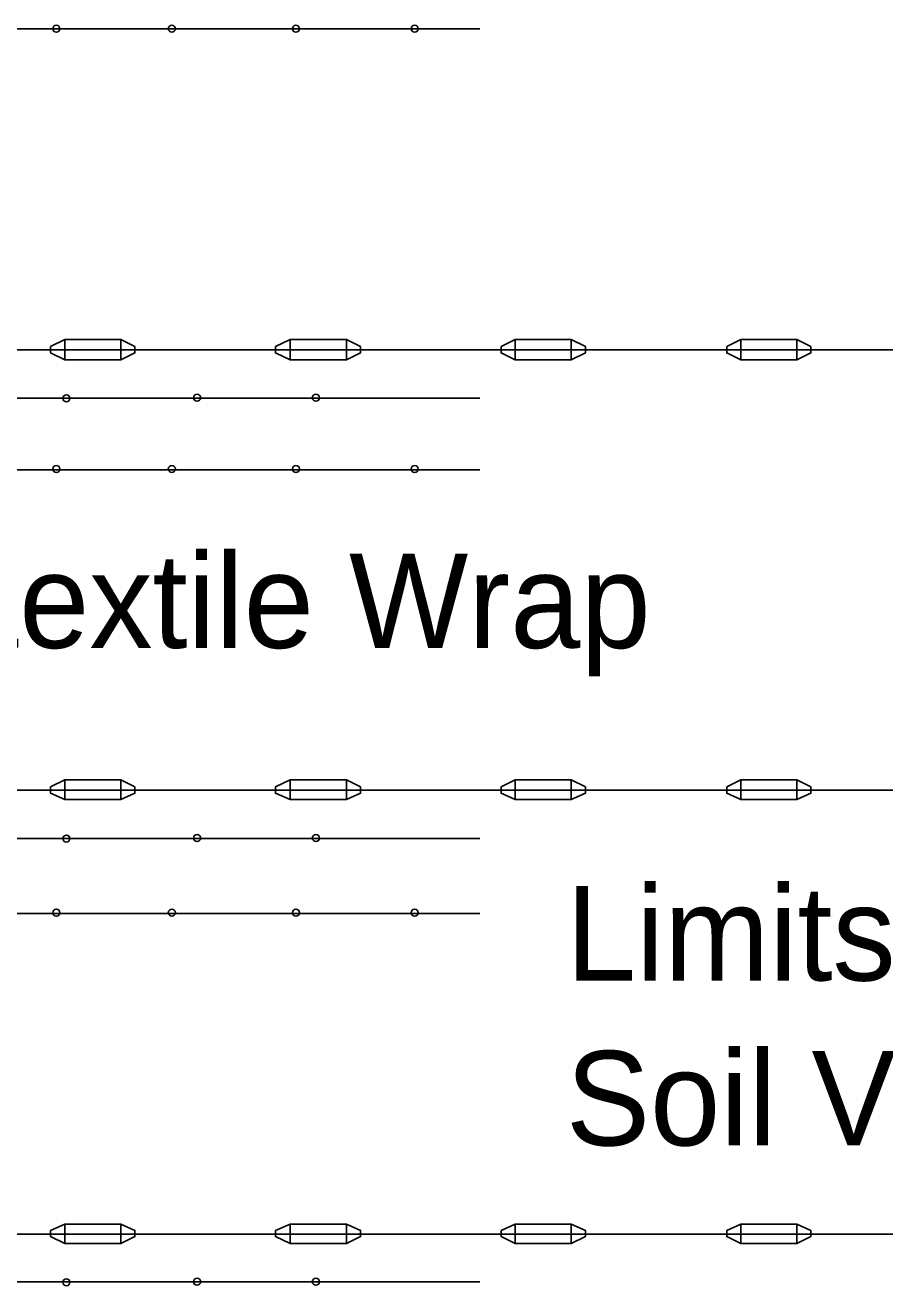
# Model space of a CAD drawing. Extents: x 126777.1 to 126780.68, y 176294.14 to 176295.44.
# Drawn here: x 126779.2844 to 126779.3418, y 176295.1145 to 176295.1986 of the extents above; entities that cross this region are included whole.
import ezdxf

# ---------------------------------------------------------------- set-up
doc = ezdxf.new("R2010")
doc.units = 0
for name, color, linetype in [('Miscellaneous', 7, 'Continuous'), ('Patterning', 7, 'Continuous'), ('TextMisc', 7, 'Continuous')]:
    doc.layers.add(name, color=color, linetype=linetype)

msp = doc.modelspace()

# ---------------------------------------------------------------- linework, layer by layer
at = {"layer": 'Miscellaneous'}
for p, q in [((126779.24097118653, 176295.17692708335), (126779.3821691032, 176295.17692708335)), ((126779.24097118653, 176295.14755208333), (126779.3821691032, 176295.14755208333)), ((126779.24097118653, 176295.11791666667), (126779.3821691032, 176295.11791666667))]:
    msp.add_line(p, q, dxfattribs=at)
for points in [[(126779.28612743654, 176295.17713541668), (126779.28706493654, 176295.17760416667), (126779.28706493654, 176295.17625000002), (126779.28612743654, 176295.17671875)], [(126779.28706493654, 176295.17760416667), (126779.29081493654, 176295.17760416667), (126779.29081493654, 176295.17625000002), (126779.28706493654, 176295.17625000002)], [(126779.29081493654, 176295.17760416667), (126779.29175243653, 176295.17713541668), (126779.29175243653, 176295.17671875), (126779.29081493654, 176295.17625000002)], [(126779.30112743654, 176295.17713541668), (126779.30211701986, 176295.17760416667), (126779.30211701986, 176295.17625000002), (126779.30112743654, 176295.17671875)], [(126779.30211701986, 176295.17760416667), (126779.30586701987, 176295.17760416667), (126779.30586701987, 176295.17625000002), (126779.30211701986, 176295.17625000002)], [(126779.30586701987, 176295.17760416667), (126779.30680451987, 176295.17713541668), (126779.30680451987, 176295.17671875), (126779.30586701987, 176295.17625000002)], [(126779.31617951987, 176295.17713541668), (126779.31711701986, 176295.17760416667), (126779.31711701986, 176295.17625000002), (126779.31617951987, 176295.17671875)], [(126779.31711701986, 176295.17760416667), (126779.32086701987, 176295.17760416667), (126779.32086701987, 176295.17625000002), (126779.31711701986, 176295.17625000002)], [(126779.32086701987, 176295.17760416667), (126779.32180451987, 176295.17713541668), (126779.32180451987, 176295.17671875), (126779.32086701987, 176295.17625000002)], [(126779.3312316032, 176295.17713541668), (126779.3321691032, 176295.17760416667), (126779.3321691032, 176295.17625000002), (126779.3312316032, 176295.17671875)], [(126779.3321691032, 176295.17760416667), (126779.3359191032, 176295.17760416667), (126779.3359191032, 176295.17625000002), (126779.3321691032, 176295.17625000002)], [(126779.3359191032, 176295.17760416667), (126779.3368566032, 176295.17713541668), (126779.3368566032, 176295.17671875), (126779.3359191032, 176295.17625000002)], [(126779.28612743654, 176295.14776041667), (126779.28706493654, 176295.14822916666), (126779.28706493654, 176295.14692708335), (126779.28612743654, 176295.14734375)], [(126779.28706493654, 176295.14822916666), (126779.29081493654, 176295.14822916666), (126779.29081493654, 176295.14692708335), (126779.28706493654, 176295.14692708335)], [(126779.29081493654, 176295.14822916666), (126779.29175243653, 176295.14776041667), (126779.29175243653, 176295.14734375), (126779.29081493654, 176295.14692708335)], [(126779.30112743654, 176295.14776041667), (126779.30211701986, 176295.14822916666), (126779.30211701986, 176295.14692708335), (126779.30112743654, 176295.14734375)], [(126779.30211701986, 176295.14822916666), (126779.30586701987, 176295.14822916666), (126779.30586701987, 176295.14692708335), (126779.30211701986, 176295.14692708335)], [(126779.30586701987, 176295.14822916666), (126779.30680451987, 176295.14776041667), (126779.30680451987, 176295.14734375), (126779.30586701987, 176295.14692708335)], [(126779.31617951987, 176295.14776041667), (126779.31711701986, 176295.14822916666), (126779.31711701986, 176295.14692708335), (126779.31617951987, 176295.14734375)], [(126779.31711701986, 176295.14822916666), (126779.32086701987, 176295.14822916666), (126779.32086701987, 176295.14692708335), (126779.31711701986, 176295.14692708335)], [(126779.32086701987, 176295.14822916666), (126779.32180451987, 176295.14776041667), (126779.32180451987, 176295.14734375), (126779.32086701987, 176295.14692708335)], [(126779.3312316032, 176295.14776041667), (126779.3321691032, 176295.14822916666), (126779.3321691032, 176295.14692708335), (126779.3312316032, 176295.14734375)], [(126779.3321691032, 176295.14822916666), (126779.3359191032, 176295.14822916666), (126779.3359191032, 176295.14692708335), (126779.3321691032, 176295.14692708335)], [(126779.3359191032, 176295.14822916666), (126779.3368566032, 176295.14776041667), (126779.3368566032, 176295.14734375), (126779.3359191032, 176295.14692708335)], [(126779.28612743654, 176295.11817708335), (126779.28706493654, 176295.11859375), (126779.28706493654, 176295.11729166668), (126779.28612743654, 176295.11776041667)], [(126779.28706493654, 176295.11859375), (126779.29081493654, 176295.11859375), (126779.29081493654, 176295.11729166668), (126779.28706493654, 176295.11729166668)], [(126779.29081493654, 176295.11859375), (126779.29175243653, 176295.11817708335), (126779.29175243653, 176295.11776041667), (126779.29081493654, 176295.11729166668)], [(126779.30112743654, 176295.11817708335), (126779.30211701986, 176295.11859375), (126779.30211701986, 176295.11729166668), (126779.30112743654, 176295.11776041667)], [(126779.30211701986, 176295.11859375), (126779.30586701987, 176295.11859375), (126779.30586701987, 176295.11729166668), (126779.30211701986, 176295.11729166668)], [(126779.30586701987, 176295.11859375), (126779.30680451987, 176295.11817708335), (126779.30680451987, 176295.11776041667), (126779.30586701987, 176295.11729166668)], [(126779.31617951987, 176295.11817708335), (126779.31711701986, 176295.11859375), (126779.31711701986, 176295.11729166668), (126779.31617951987, 176295.11776041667)], [(126779.31711701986, 176295.11859375), (126779.32086701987, 176295.11859375), (126779.32086701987, 176295.11729166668), (126779.31711701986, 176295.11729166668)], [(126779.32086701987, 176295.11859375), (126779.32180451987, 176295.11817708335), (126779.32180451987, 176295.11776041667), (126779.32086701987, 176295.11729166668)], [(126779.3312316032, 176295.11817708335), (126779.3321691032, 176295.11859375), (126779.3321691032, 176295.11729166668), (126779.3312316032, 176295.11776041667)], [(126779.3321691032, 176295.11859375), (126779.3359191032, 176295.11859375), (126779.3359191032, 176295.11729166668), (126779.3321691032, 176295.11729166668)], [(126779.3359191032, 176295.11859375), (126779.3368566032, 176295.11817708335), (126779.3368566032, 176295.11776041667), (126779.3359191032, 176295.11729166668)]]:
    msp.add_lwpolyline(points, close=True, dxfattribs=at)
at = {"layer": 'Patterning'}
for p, q in [((126779.31477326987, 176295.19833333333), (126779.25581493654, 176295.19833333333)), ((126779.2410753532, 176295.17369791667), (126779.31477326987, 176295.17369791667)), ((126779.31477326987, 176295.16890625), (126779.25581493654, 176295.16890625)), ((126779.2410753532, 176295.14432291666), (126779.31477326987, 176295.14432291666)), ((126779.31477326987, 176295.1393229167), (126779.25581493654, 176295.1393229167)), ((126779.2410753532, 176295.11473958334), (126779.31477326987, 176295.11473958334))]:
    msp.add_line(p, q, dxfattribs=at)
for centre, radius, start, end in [((126779.28650547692, 176295.19834467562), 0.00023464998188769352, 0, 180), ((126779.28650547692, 176295.19834467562), 0.00023464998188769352, 180, 0), ((126779.2942136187, 176295.19834467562), 0.0002346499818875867, 0, 180), ((126779.2942136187, 176295.19834467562), 0.0002346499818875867, 180, 0), ((126779.30249415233, 176295.19834467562), 0.00023464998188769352, 0, 180), ((126779.30249415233, 176295.19834467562), 0.00023464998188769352, 180, 0), ((126779.31041589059, 176295.19834467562), 0.00023464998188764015, 0, 180), ((126779.31041589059, 176295.19834467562), 0.00023464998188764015, 180, 0), ((126779.28717844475, 176295.17368753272), 0.00023464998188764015, 0, 180), ((126779.29590189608, 176295.17372518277), 0.00023464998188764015, 0, 180), ((126779.30382363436, 176295.17372518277), 0.00023464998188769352, 0, 180), ((126779.28717844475, 176295.17368753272), 0.00023464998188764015, 180, 0), ((126779.29590189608, 176295.17372518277), 0.00023464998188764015, 180, 0), ((126779.30382363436, 176295.17372518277), 0.00023464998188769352, 180, 0), ((126779.28650547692, 176295.16897071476), 0.00023464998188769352, 0, 180), ((126779.28650547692, 176295.16897071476), 0.00023464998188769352, 180, 0), ((126779.2942136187, 176295.16897071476), 0.0002346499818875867, 0, 180), ((126779.2942136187, 176295.16897071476), 0.0002346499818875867, 180, 0), ((126779.30249415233, 176295.16897071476), 0.00023464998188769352, 0, 180), ((126779.30249415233, 176295.16897071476), 0.00023464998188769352, 180, 0), ((126779.31041589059, 176295.16897071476), 0.00023464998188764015, 0, 180), ((126779.31041589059, 176295.16897071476), 0.00023464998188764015, 180, 0), ((126779.28717844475, 176295.14431357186), 0.00023464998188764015, 0, 180), ((126779.29590189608, 176295.14435122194), 0.00023464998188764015, 0, 180), ((126779.30382363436, 176295.14435122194), 0.00023464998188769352, 0, 180), ((126779.28717844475, 176295.14431357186), 0.00023464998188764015, 180, 0), ((126779.29590189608, 176295.14435122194), 0.00023464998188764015, 180, 0), ((126779.30382363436, 176295.14435122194), 0.00023464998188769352, 180, 0), ((126779.28650547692, 176295.13937250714), 0.00023464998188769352, 0, 180), ((126779.2942136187, 176295.13937250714), 0.0002346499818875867, 0, 180), ((126779.30249415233, 176295.13937250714), 0.00023464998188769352, 0, 180), ((126779.31041589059, 176295.13937250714), 0.00023464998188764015, 0, 180), ((126779.28650547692, 176295.13937250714), 0.00023464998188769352, 180, 0), ((126779.2942136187, 176295.13937250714), 0.0002346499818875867, 180, 0), ((126779.30249415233, 176295.13937250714), 0.00023464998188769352, 180, 0), ((126779.31041589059, 176295.13937250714), 0.00023464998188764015, 180, 0), ((126779.28717844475, 176295.1147153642), 0.00023464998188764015, 0, 180), ((126779.28717844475, 176295.1147153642), 0.00023464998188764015, 180, 0), ((126779.29590189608, 176295.1147530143), 0.00023464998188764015, 0, 180), ((126779.29590189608, 176295.1147530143), 0.00023464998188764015, 180, 0), ((126779.30382363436, 176295.1147530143), 0.00023464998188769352, 0, 180), ((126779.30382363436, 176295.1147530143), 0.00023464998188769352, 180, 0)]:
    msp.add_arc(centre, radius, start, end, dxfattribs=at)

# ---------------------------------------------------------------- texts
at = {"layer": 'TextMisc'}
for s, p in [('Geotextile Wrap', (126779.2657628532, 176295.15703125)), ('Limits of ', (126779.32050324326, 176295.13484582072)), ('Soil Volume', (126779.32050324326, 176295.12384579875))]:
    msp.add_text(s, height=0.0063000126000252, dxfattribs=at).set_placement(p)

doc.saveas('drawing.dxf')
